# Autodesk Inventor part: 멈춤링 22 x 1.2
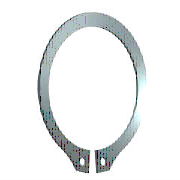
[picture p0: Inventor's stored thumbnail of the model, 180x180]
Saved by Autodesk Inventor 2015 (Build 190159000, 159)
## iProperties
IsCustomPart: 0
Company: 한국ATC센터
Created: 2014-07
Part Number: 멈춤링 22 x 1.2
Material: Steel, Mild
Description: 리테이닝 링(C형)
Document SubType Name: Modeling
Standard: KS B 1336
Designer: KYOUNG IL JANG
Standards Organization: KS
Language: ko-KR
Size Designation: 22 x 1.2
Categories: <MemberInstance><Categories><Category DisplayName="샤프트 부품" InternalName="7f7aeb1f-a693-4053-b835-cee3144e0d98" Mnemonic="SHFT"><Category DisplayName="써클립" Inter
Density: 7.85 g/cm^3
Appearance: Steel
Mass: 1.82627 g
Surface Area: 5.91219 cm^2
Volume: 0.232646 cm^3
Author: KYOUNG IL JANG
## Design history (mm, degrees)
sketch "스케치1"
  geometry: L1 (-6, 0)-(6, 0) reference; L2 (0, 20.189)-(0, -80.536) reference; L3 (-48.09, 0)-(48.09, 0) reference; L4 (-0.5, -21.488)-(-0.5, -25.588); L5 (-0.5, -6.54)-(-0.5, -13.29); L6 (-2.795, 2.7)-(3.672, 2.7); L7 (0.5, -6.54)-(0.5, -13.29); L8 (0.5, -21.488)-(0.5, -25.588); C1 r 1 at (-2, -23.437); C2 r 1 at (2, -23.437); A1 r 10.5 centre (0, -11) between (0.5, -21.488) and (-0.5, -21.488); A2 r 13.025 centre (0, -10.325) between (5.149, -22.289) and (-5.149, -22.289); A3 r 14.597 centre (0, -11) between (-2.318, -25.411) and (-0.5, -25.588); A4 r 2 centre (-2, -23.437) between (-3.97, -23.781) and (-2.318, -25.411); A5 r 2 centre (-5.94, -24.126) between (-3.97, -23.781) and (-5.149, -22.289); A6 r 2 centre (5.94, -24.126) between (5.149, -22.289) and (3.97, -23.781); A7 r 2 centre (2, -23.437) between (2.318, -25.411) and (3.97, -23.781); A8 r 14.597 centre (0, -11) between (0.5, -25.588) and (2.318, -25.411)
  constraints: 16 point on circle, 12 end point, 10 centre point, 9 symmetric about line, 5 point on line, 4 tangent, 3 coincident, 2 horizontal, 1 perpendicular, 1 vertical, 5 other
  dimensions: "d0" = 21 diameter of A1 (= ND); "d1" = 4.1 distance of L4.end L4.start (= SRB2); "d6" = 0.5 distance between parallel lines of L2 L5 (= 0.25 x SD5); "d7" = 2.7 distance between parallel lines of L6 L3 (= SRB1); "d8" = 0.675 distance of A1.centre A2.centre (= 0.25 x SRB1); "d9" = 2 radius of A4 (= SD5); "d10" = 2 radius of A5 (= SD5); "d11" = 1.5 distance from line of L4 A4.centre (= 0.75 x SD5); "d12" = 2 diameter of C1 (= SD5); "d13" = 2 diameter of C2 (= SD5); "d14" = 11 distance from line of A1.centre L1 (= 0.5 x WD)
extrude "본체" new body sketch "스케치1" distance "d2" = 1.2 (= SD); taper "d3" = 0 deg
workaxis "Work Axis1"
workplane "Work Plane1"
body "Solid1"
other parameters: "WD" = 22 (= WDMIN) [user parameter; used in 1 equation term], "SD" = 1.2 [user parameter; used in 1 equation term], "SRB1" = 2.7 [user parameter; used in 2 equation terms], "ND" = 21 [user parameter; used in 1 equation term], "SRB2" = 4.1 [user parameter; used in 1 equation term], "SD5" = 2 [user parameter; used in 6 equation terms], "d15" = 0, "d16" = 0, "d17" = 0, "d41" = 0, "d42" = 0, "WDMIN" = 22 [user parameter; used in 1 equation term], "SD3" = 20.5 [user parameter], "WDMAX" = 24 [user parameter]
